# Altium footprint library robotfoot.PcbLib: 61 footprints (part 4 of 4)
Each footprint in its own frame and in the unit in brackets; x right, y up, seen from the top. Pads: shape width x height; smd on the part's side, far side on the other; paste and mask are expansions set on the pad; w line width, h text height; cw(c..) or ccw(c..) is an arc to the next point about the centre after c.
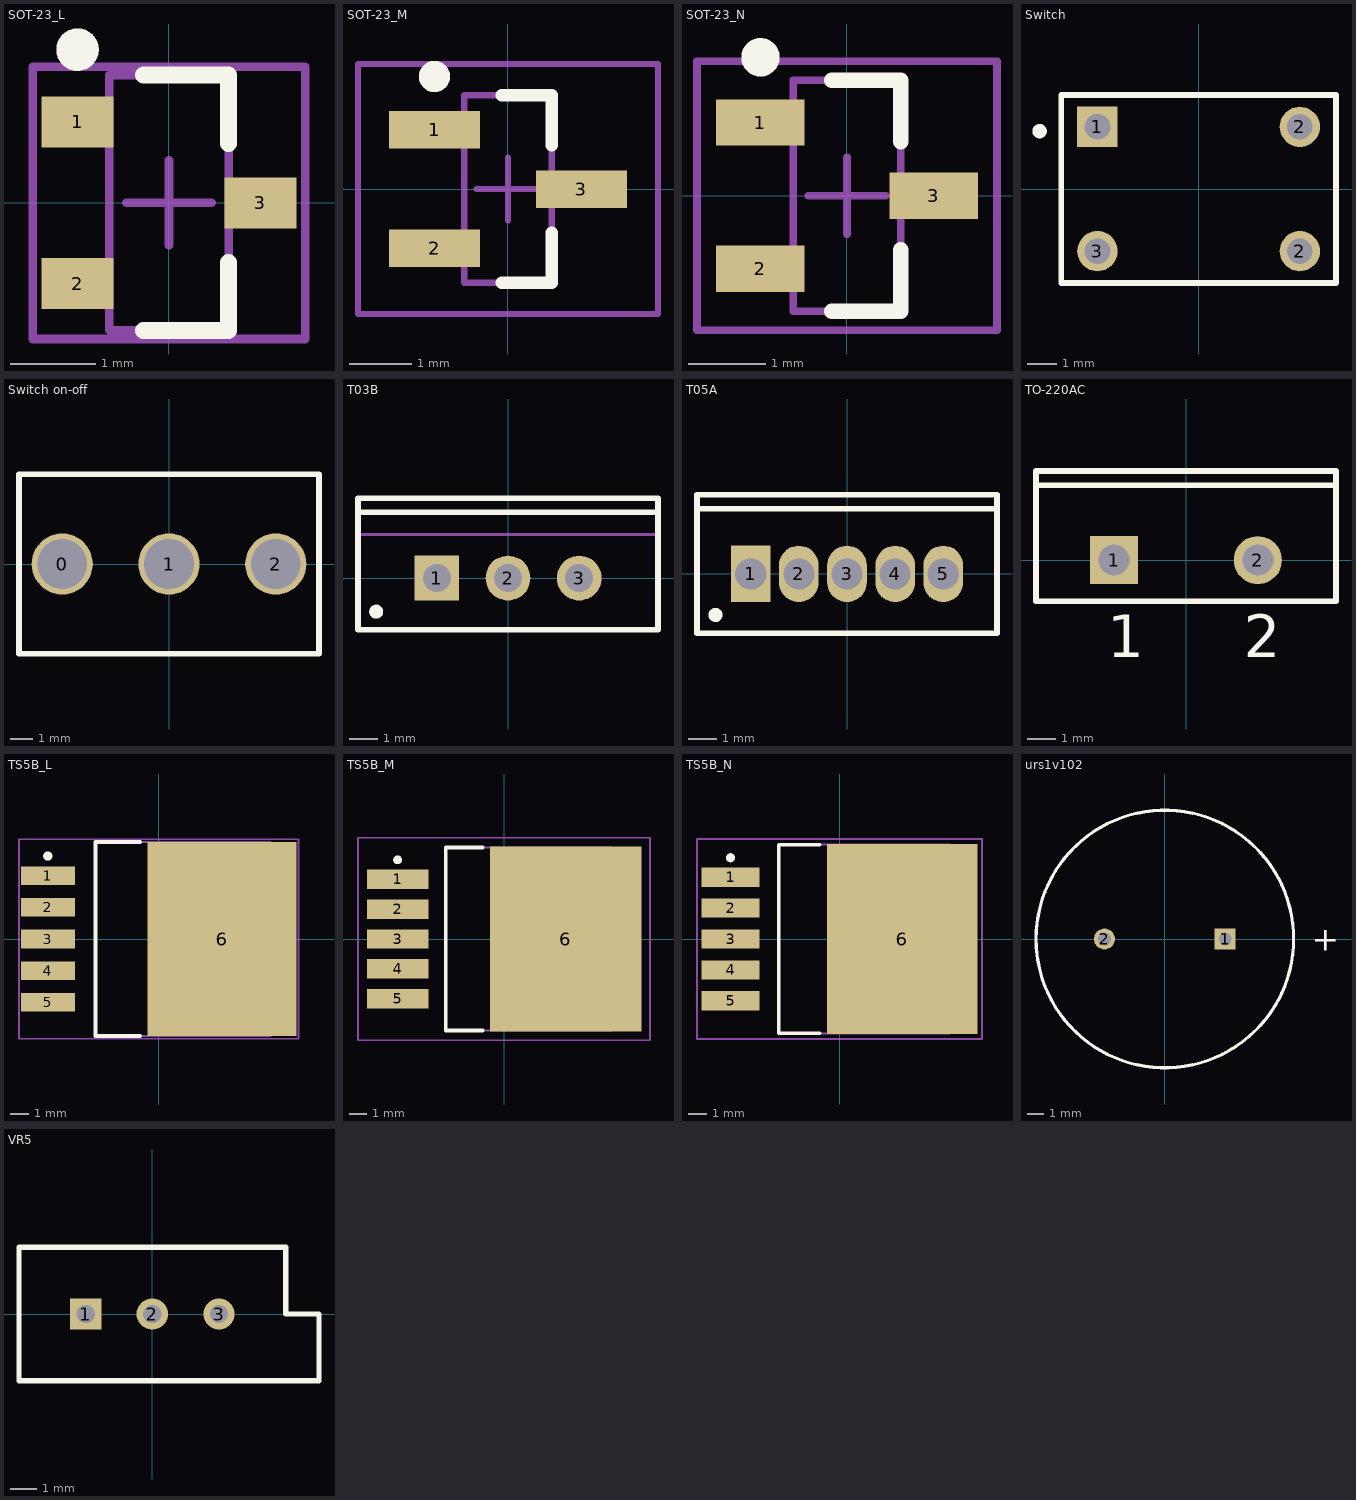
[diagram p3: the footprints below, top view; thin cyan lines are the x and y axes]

## SOT-23_L [mm] "SOT23, 3-Leads, Body 2.9x1.3mm, Pitch 0.95mm, Lead Span 2.5mm, IPC High Density"
height 1.1
pads (3):
  rect 0.85x0.6 smd: 1(-1.075,0.95) 2(-1.075,-0.95) 3(1.075,0)
Top Overlay:
  circle w0.25: c-1.075,1.8 r0.125
  lines w0.2: -0.3,-1.5 0.7,-1.5 0.7,-0.7 ; -0.3,1.5 0.7,1.5 0.7,0.7
Mechanical 13:
  lines w0.1: -0.7,-1.5 -0.7,1.5 0.7,1.5 0.7,-1.5 -0.7,-1.5
Mechanical 15:
  lines w0.1: -0.5,0 0.5,0 ; 0,-0.5 0,0.5 ; -1.6,-1.6 -1.6,1.6 1.6,1.6 1.6,-1.6 -1.6,-1.6
3D body: height 1.1, standoff 0, extent -0.7,-1.5 0.7,1.5

## SOT-23_M [mm] "SOT23, 3-Leads, Body 2.9x1.3mm, Pitch 0.95mm, Lead Span 2.5mm, IPC Low Density"
height 1.1
pads (3):
  rect 1.45x0.6 smd: 1(-1.175,0.95) 2(-1.175,-0.95) 3(1.175,0)
Top Overlay:
  circle w0.25: c-1.175,1.8 r0.125
  lines w0.2: -0.1,-1.5 0.7,-1.5 0.7,-0.7 ; -0.1,1.5 0.7,1.5 0.7,0.7
Mechanical 13:
  lines w0.1: -0.7,-1.5 0.7,-1.5 0.7,1.5 -0.7,1.5 -0.7,-1.5
Mechanical 15:
  lines w0.1: -0.5,0 0.5,0 ; 0,-0.5 0,0.5 ; -2.4,-2 2.4,-2 2.4,2 -2.4,2 -2.4,-2
3D body: height 1.1, standoff 0, extent -0.7,-1.5 0.7,1.5

## SOT-23_N [mm] "SOT23, 3-Leads, Body 2.9x1.3mm, Pitch 0.95mm, Lead Span 2.5mm, IPC Medium Density"
height 1.1
pads (3):
  rect 1.15x0.6 smd: 1(-1.125,0.95) 2(-1.125,-0.95) 3(1.125,0)
Top Overlay:
  circle w0.25: c-1.125,1.8 r0.125
  lines w0.2: -0.2,-1.5 0.7,-1.5 0.7,-0.7 ; -0.2,1.5 0.7,1.5 0.7,0.7
Mechanical 13:
  lines w0.1: -0.7,-1.5 0.7,-1.5 0.7,1.5 -0.7,1.5 -0.7,-1.5
Mechanical 15:
  lines w0.1: -0.5,0 0.5,0 ; 0,-0.5 0,0.5 ; -1.95,-1.75 1.95,-1.75 1.95,1.75 -1.95,1.75 -1.95,-1.75
3D body: height 1.1, standoff 0, extent -0.7,-1.5 0.7,1.5

## Switch [mil] "Switch button"
pads (4):
  rect 55x55 hole 35: 1(-137.8,84.65)
  round 55 hole 35: 2(137.8,-84.65) 2(137.8,84.65) 3(-137.8,-84.65)
Top Overlay:
  circle w9.84: c-216.54,78.74 r4.92
  lines w7.87: -187.01,-127.95 187.01,-127.95 187.01,127.95 -187.01,127.95 -187.01,-127.95

## Switch on-off [mil]
pads (3):
  round 106 hole 86: 0(-185.04,0) 1(0,0) 2(185.04,0)
Top Overlay:
  lines w10: -259.84,-155.51 -259.84,155.51 259.84,155.51 259.84,-155.51 -259.84,-155.51

## T03B [mm] "TO, Thru-Hole, Vertical, Heatsink Mounted; 3 In-Line Leads; Pitch 2.54 mm"
height 19.4
pads (3):
  rect 1.6x1.6 hole 1: 1(-2.54,0)
  round 1.6 hole 1: 2(0,0) 3(2.54,0)
Top Overlay:
  circle w0.25: c-4.7,-1.2 r0.125
  lines w0.2: -5.35,2.35 5.35,2.35 ; -5.35,-1.85 5.35,-1.85 5.35,2.85 -5.35,2.85 -5.35,-1.85
Mechanical 13:
  lines w0.1: -5.35,1.55 5.35,1.55 ; -5.35,-1.85 -5.35,2.85 5.35,2.85 5.35,-1.85 -5.35,-1.85
Mechanical 15:
  lines w0.1: -0.5,0 0.5,0 ; 0,-0.5 0,0.5
3D body: height 19.4, standoff 12.9, extent -5.349,1.551 5.349,2.849
3D body: height 12.9, standoff 4, extent -5.4,-1.9 5.4,2.9

## T05A [mm] "TO, Thru-Hole, Vertical, Heatsink Mounted; 5 In-Line Leads; Pitch 1.70 mm"
height 19.6
pads (5):
  rect 1.4x2 hole 1.1: 1(-3.4,0)
  oval 1.4x2 hole 1.1: 2(-1.7,0) 3(0,0) 4(1.7,0) 5(3.4,0)
Top Overlay:
  circle w0.25: c-4.65,-1.45 r0.125
  lines w0.2: -5.3,2.3 5.3,2.3 ; -5.3,-2.1 5.3,-2.1 5.3,2.8 -5.3,2.8 -5.3,-2.1
Mechanical 13:
  lines w0.1: -5.3,2.3 5.3,2.3 ; -5.3,-2.1 -5.3,2.8 5.3,2.8 5.3,-2.1 -5.3,-2.1 ; -3.91,-0.28 -3.91,0.28 -2.89,0.28 -2.89,-0.28 -3.91,-0.28 ; -2.21,-0.28 -2.21,0.28 -1.19,0.28 -1.19,-0.28 -2.21,-0.28 ; -0.51,-0.28 -0.51,0.28 0.51,0.28 0.51,-0.28 -0.51,-0.28 ; 1.19,-0.28 1.19,0.28 2.21,0.28 2.21,-0.28 1.19,-0.28 ; 2.89,-0.28 2.89,0.28 3.91,0.28 3.91,-0.28 2.89,-0.28
Mechanical 15:
  lines w0.1: -0.5,0 0.5,0 ; 0,-0.5 0,0.5
3D body: height 13, standoff 4.1, extent -5.35,-2.15 5.35,2.85
3D body: height 19.6, standoff 13, extent -5.299,2.301 5.299,2.799
3D body: height 4.1, standoff 0, extent -3.909,-0.279 -2.891,0.279
3D body: height 4.1, standoff 0, extent -2.209,-0.279 -1.191,0.279
3D body: height 4.1, standoff 0, extent 1.191,-0.279 2.209,0.279
3D body: height 4.1, standoff 0, extent 2.891,-0.279 3.909,0.279
3D body: height 4.1, standoff 0, extent -0.509,-0.279 0.509,0.279

## TO-220AC [mm] "TO, Thru-Hole, Vertical, Heatsink Mounted; 3 In-Line Leads (1 Absent); Pitch 2.54 mm"
height 19.2
pads (2):
  rect 1.7x1.7 hole 1.1: 1(-2.54,0)
  round 1.7 hole 1.1: 2(2.54,0)
Top Overlay:
  lines w0.2: -5.3,2.65 5.3,2.65 ; -5.3,-1.45 5.3,-1.45 5.3,3.15 -5.3,3.15 -5.3,-1.45
  text "1" at -2.79,-3.425 h1.5
  text "2" at 2.04,-3.425 h1.5

## TS5B_L [mm] "D2-PAK, 6-Leads, Body 8.6x10.2mm, Pitch 1.7mm, Lead Span 14.1mm, IPC High Density"
height 4.65
pads (6):
  rect 2.9x1 smd: 1(-5.95,3.4) 2(-5.95,1.7) 3(-5.95,0) 4(-5.95,-1.7) 5(-5.95,-3.4)
  rect 8x10.4 smd: 6(3.4,0)
Top Overlay:
  circle w0.25: c-5.95,4.45 r0.125
  lines w0.2: -1,-5.2 -3.4,-5.2 -3.4,5.2 -1,5.2
Mechanical 13:
  lines w0.1: -3.4,-5.2 -3.4,5.2 6,5.2 6,-5.2 -3.4,-5.2
Mechanical 15:
  lines w0.1: -0.5,0 0.5,0 ; 0,-0.5 0,0.5 ; -7.5,-5.35 -7.5,5.35 7.5,5.35 7.5,-5.35 -7.5,-5.35
3D body: height 4.65, standoff 0, extent -3.4,-5.2 6,5.2

## TS5B_M [mm] "D2-PAK, 6-Leads, Body 8.6x10.2mm, Pitch 1.7mm, Lead Span 14.1mm, IPC Low Density"
height 4.65
pads (6):
  rect 3.5x1.1 smd: 1(-6.05,3.4) 2(-6.05,1.7) 3(-6.05,0) 4(-6.05,-1.7) 5(-6.05,-3.4)
  rect 8.6x10.5 smd: 6(3.5,0)
Top Overlay:
  circle w0.25: c-6.05,4.5 r0.125
  lines w0.2: -1.2,-5.2 -3.3,-5.2 -3.3,5.2 -1.2,5.2
Mechanical 13:
  lines w0.1: -3.3,-5.2 6.1,-5.2 6.1,5.2 -3.3,5.2 -3.3,-5.2
Mechanical 15:
  lines w0.1: -0.5,0 0.5,0 ; 0,-0.5 0,0.5 ; -8.3,-5.75 8.3,-5.75 8.3,5.75 -8.3,5.75 -8.3,-5.75
3D body: height 4.65, standoff 0, extent -3.3,-5.2 6.1,5.2

## TS5B_N [mm] "D2-PAK, 6-Leads, Body 8.6x10.2mm, Pitch 1.7mm, Lead Span 14.1mm, IPC Medium Density"
height 4.65
pads (6):
  rect 3.2x1.05 smd: 1(-6,3.4) 2(-6,1.7) 3(-6,0) 4(-6,-1.7) 5(-6,-3.4)
  rect 8.3x10.45 smd: 6(3.45,0)
Top Overlay:
  circle w0.25: c-6,4.475 r0.125
  lines w0.2: -1.1,-5.2 -3.35,-5.2 -3.35,5.2 -1.1,5.2
Mechanical 13:
  lines w0.1: -3.35,-5.2 -3.35,5.2 6.05,5.2 6.05,-5.2 -3.35,-5.2
Mechanical 15:
  lines w0.1: -0.5,0 0.5,0 ; 0,-0.5 0,0.5 ; -7.85,-5.5 -7.85,5.5 7.85,5.5 7.85,-5.5 -7.85,-5.5
3D body: height 4.65, standoff 0, extent -3.35,-5.2 6.05,5.2

## urs1v102 [mm] "Polarized Capacitor (Radial); 2 Leads"
pads (2):
  rect 1.3x1.3 hole 0.8: 1(3.75,0)
  round 1.3 hole 0.8: 2(-3.75,0)
Top Overlay:
  circle w0.2: c0,0 r8
  text "+" at 9.132,-0.737 h1.5

## VR5 [mm] "Thru-Hole; 3 Leads"
pads (3):
  rect 1.2x1.2 hole 0.7: 1(-2.54,0)
  round 1.2 hole 0.7: 2(0,0) 3(2.54,0)
Top Overlay:
  lines w0.2: -5.08,-2.54 6.35,-2.54 6.35,0 5.08,0 5.08,2.54 -5.08,2.54 -5.08,-2.54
